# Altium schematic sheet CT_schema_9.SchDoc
size 287 x 160 mm
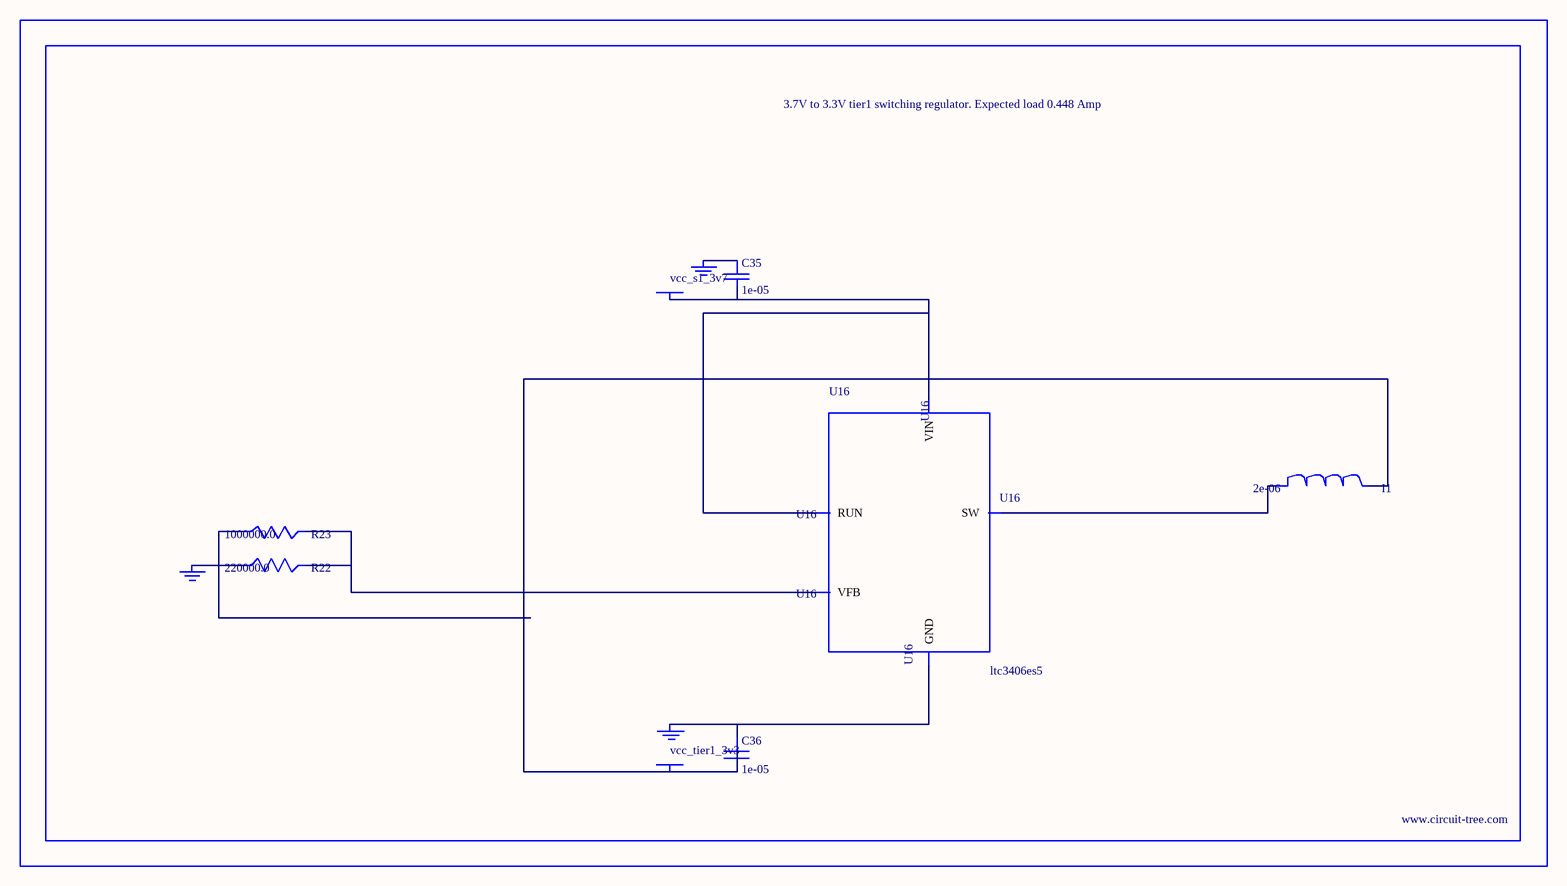
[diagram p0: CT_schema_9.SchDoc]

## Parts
BORDER8  (no value)
C35  1e-05  [C0805]
C36  1e-05  [C0805]
GND_INSTANCE_8_0  (no value)
GND_INSTANCE_8_1  (no value)
GND_INSTANCE_8_2  (no value)
I1  2e-06  [WE-HCI_7030/7040/7050]
POWER_INSTANCE_8_0  vcc_tier1_3v3
POWER_INSTANCE_8_1  vcc_s1_3v7
R22  220000.0  [R0603]
R23  1000000.0  [R0603]
U16  ltc3406es5  [TSOT-23-5]

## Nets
NetC35_1: C35.1 GND_INSTANCE_8_1.0(GND)
NetC35_2: C35.2 POWER_INSTANCE_8_1.0(PWR) U16.1(RUN) U16.4(VIN)
NetC36_1: C36.1 GND_INSTANCE_8_0.0(GND) U16.2(GND)
NetC36_2: C36.2 I1.2 POWER_INSTANCE_8_0.0(PWR) R23.1
NetGND_INSTANCE_8_2_0: GND_INSTANCE_8_2.0(GND) R22.1
NetI1_1: I1.1 U16.3(SW)
NetR22_2: R22.2 R23.2 U16.5(VFB)

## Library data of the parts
BORDER8 = BORDER_PAGE8
C35 C36 = C0805C106K8RACTU
GND_INSTANCE_8_0-GND_INSTANCE_8_2 = GND
I1 = 744314200
POWER_INSTANCE_8_0 POWER_INSTANCE_8_1 = PWR
R22 = RC0603JR-07220KL
R23 = RC0603JR-071ML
